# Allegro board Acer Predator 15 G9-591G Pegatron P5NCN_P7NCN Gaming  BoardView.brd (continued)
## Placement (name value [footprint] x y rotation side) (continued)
Q8804  -  [VX_SOIC_8P_50_197X236]  231.7 13.43 270 top
Q8805  -  [VX_SOT23_H43]  220.14 36.92 270 top
Q8806  -  [VX_SOT23_H43]  219.38 47.72 270 bottom
Q8807  -  [VX_SOT23_H43]  222.3 41.62 180 bottom
Q8900  -  [VX_SOP_8P_SPE_FAIRCHILD]  171.42 84.05 0 bottom
Q8901  -  [VX_SOP_8P_SPE_FAIRCHILD]  165.28 84.29 180 top
Q9100  -  [VX_SOT23_2D4_H44]  151.64 46.83 180 top
Q9101  -  [VX_SOT353]  148.51 44.8 180 top
Q9102  -  [VX_SOT353]  148.01 39.97 270 top
Q9103  -  [VX_SOT353]  143.31 32.98 270 top
Q9104  -  [VX_SOT353]  211 84.53 270 bottom
Q9105  -  [VX_SOT23_2D4_H44]  197.26 78.82 180 top
Q9200  -  [VX_SC70_S6]  139.37 49.67 270 top
R300  -  [VX_R0402_0OHM_SMALL]  176.9 151.37 270 top
R0300  -  [VX_R0402_SMALL]  61.77 150.97 180 top
R0301  -  [VX_R0402_SMALL]  63.83 145.13 270 top
R301  -  [VX_R0603_0OHM_H28_SMALL]  179 148.38 0 top
R0302  -  [VX_R0402_SMALL]  57.58 144.24 180 top
R0305  -  [VX_R0402_SMALL]  64.69 145.13 90 top
R0306  -  [VX_R0402_SMALL]  61.85 145.13 270 top
R0307  -  [VX_R0402_SMALL]  62.69 145.13 90 top
R400  -  [VX_R0603_0OHM_H28_SMALL]  208.12 150.59 90 top
R401  -  [VX_R0402_0OHM_SMALL]  209.19 150.26 270 top
R0500  -  [VX_R0402_SMALL]  9.73 126.79 90 top
R0501  -  [VX_R0402_0OHM_SMALL]  11.46 126.79 270 top
R0502  -  [VX_R0603_H24_SMALL]  14.5 126.56 90 top
R0503  -  [VX_R0402_SMALL]  8.84 126.79 270 top
R0504  -  [VX_R0402_SMALL]  67.62 122.67 180 bottom
R0505  -  [VX_R0603_H24_SMALL]  13.26 122.57 180 top
R0506  -  [VX_R0402_SMALL]  67.62 120.89 180 bottom
R0507  -  [VX_R0402_SMALL]  67.62 120 0 bottom
R0508  -  [VX_R0603_H24_SMALL]  14.07 128.84 180 top
R0509  -  [VX_R0402_SMALL]  16.05 128.44 90 top
R0510  -  [VX_R0402_SMALL]  11.86 123.71 180 top
R0511  -  [VX_R0402_SMALL]  12.31 130.08 180 top
R0600  -  [VX_R0402_SMALL]  67.62 121.78 180 bottom
R0700  -  [VX_R0402_SMALL]  16.08 140.68 90 top
R0701  -  [VX_R0402_SMALL]  20.19 145.41 0 top
R0702  -  [VX_R0402_SMALL]  24.05 143.65 0 top
R0703  -  [VX_R0402_SMALL]  21.07 140 180 top
R0704  -  [VX_R0402_SMALL]  14.91 124.6 0 bottom
R0705  -  [VX_R0402_SMALL]  14.28 141.87 180 bottom
R0706  -  [VX_R0402_SMALL]  15.97 151.5 90 bottom
R0707  -  [VX_R0402_SMALL]  17.2 147.07 0 top
R0708  -  [VX_R0402_SMALL]  17.2 148.99 180 top
R0709  -  [VX_R0402_SMALL]  17.32 142.76 180 top
R0710  -  [VX_R0402_SMALL]  16.97 140.68 90 top
R0712  -  [VX_R0402_SMALL]  19.23 142.25 0 top
R0713  -  [VX_R0402_SMALL]  24.05 137.43 180 top
R0714  -  [VX_R0402_SMALL]  19.23 141.37 0 top
R0715  -  [VX_R0402_SMALL]  12.5 139.84 90 bottom
R0717  -  [VX_R0402_SMALL]  19.23 148.05 180 top
R0718  -  [VX_R0402_SMALL]  21.44 137.51 270 top
R0719  -  [VX_R0402_SMALL]  14.28 140.98 180 bottom
R0723  -  [VX_R0402_SMALL]  22.4 143.65 180 top
R0724  -  [VX_R0402_SMALL]  19.23 140.48 0 top
R0725  -  [VX_R0402_SMALL]  17.32 144.16 180 top
R0726  -  [VX_R0402_SMALL]  19.23 143.4 0 top
R0727  -  [VX_R0402_SMALL]  17.45 151.4 0 bottom
R0728  -  [VX_R0402_SMALL]  15.24 129.4 180 bottom
R0729  -  [VX_R0402_SMALL]  72.57 124.81 180 bottom
R0730  -  [VX_R0402_SMALL]  72.57 123.92 180 bottom
R0731  -  [VX_R0402_SMALL]  17.27 153.3 0 bottom
R0733  -  [VX_R0402_SMALL]  17.45 154.45 180 bottom
R0734  -  [VX_R0402_0OHM_SMALL]  17.86 123.51 270 bottom
R0736  -  [VX_R0402_SMALL]  17.67 147.51 270 bottom
R0737  -  [VX_R0402_SMALL]  19.61 150.64 0 top
R0738  -  [VX_R0402_SMALL]  16.82 149.24 270 bottom
R0739  -  [VX_R0402_SMALL]  16.83 147.51 270 bottom
R0740  -  [VX_R0402_SMALL]  17.27 152.29 180 bottom
R0741  -  [VX_R0402_SMALL]  17.32 145.56 180 bottom
R0742  -  [VX_R0402_SMALL]  16.68 143.71 90 bottom
R0743  -  [VX_R0402_SMALL]  55.68 140.3 90 top
R0744  -  [VX_R0402_SMALL]  14.28 142.76 0 bottom
R0745  -  [VX_R0402_SMALL]  21.07 138.75 0 top
R0746  -  [VX_R0201_H10]  19.23 155.46 180 bottom
R0747  -  [VX_R0402_SMALL]  16.82 150.26 90 top
R0748  -  [VX_R0402_0OHM_SMALL]  116.51 50.77 90 top
R0749  -  [VX_R0402_0OHM_SMALL]  115.62 50.77 90 top
R0750  -  [VX_R0402_0OHM_SMALL]  112.37 54.87 0 top
R0751  -  [VX_R0402_SMALL]  114.1 54.87 0 top
R0900  -  [VX_R0603_0OHM_H28_SMALL]  43.23 143.88 270 top
R0901  -  [VX_R0603_0OHM_H28_SMALL]  42.01 143.88 270 top
R1000  -  [VX_R0603_0OHM_H28_SMALL]  27.99 139.08 180 top
R1001  -  [VX_R0402_0OHM_SMALL]  68.55 125.04 270 bottom
R1002  -  [VX_R0603_0OHM_H28_SMALL]  25.58 143.78 270 top
R1003  -  [VX_R0603_0OHM_H28_SMALL]  27.99 136.54 180 top
R1004  -  [VX_R0402_SMALL]  25.32 141.87 90 top
R1005  -  [VX_R0402_0OHM_SMALL]  24.46 141.87 270 top
R1006  -  [VX_R0603_0OHM_H28_SMALL]  27.99 137.81 180 top
R1007  -  [VX_R0603_0OHM_H28_SMALL]  12.98 129.91 0 bottom
R1008  -  [VX_R0603_0OHM_H28_SMALL]  27.99 135.27 180 top
R1009  -  [VX_R0402_SMALL]  22.33 137.51 90 top
R1010  -  [VX_R0402_0OHM_SMALL]  21.87 136.24 0 top
R1011  -  [VX_R0603_0OHM_H28_SMALL]  22.56 133.52 0 top
R1012  -  [VX_R0603_0OHM_H28_SMALL]  21.78 149.24 90 top
R1013  -  [VX_R0402_SMALL]  34.09 132.6 0 top
R1014  -  [VX_R0402_SMALL]  19.23 147.07 0 top
R1015  -  [VX_R0402_SMALL]  15.84 143.71 90 bottom
R1016  -  [VX_R0402_SMALL]  17.51 143.71 90 bottom
R1017  -  [VX_R1206_H31]  90.98 107.71 180 top
R1018  -  [VX_R0402_0OHM_SMALL]  22.71 128.16 90 top
R1101  -  [VX_R0402_SMALL]  241.7 29.23 270 bottom
R1102  -  [VX_R0402_SMALL]  230.94 44.29 180 bottom
R1103  -  [VX_R0402_SMALL]  227.25 55.21 90 top
R1104  -  [VX_R0402_SMALL]  224.21 55.21 90 top
R1105  -  [VX_R0402_SMALL]  222.68 50.64 90 top
R1106  -  [VX_R0402_SMALL]  226.24 55.21 90 top
R1107  -  [VX_R0402_SMALL]  245.04 36.75 0 bottom
R1108  -  [VX_R0402_SMALL]  235.88 30.33 90 bottom
R1109  -  [VX_R0402_SMALL]  235.13 38.96 0 bottom
R1110  -  [VX_R0402_SMALL]  235.13 39.84 0 bottom
R1111  -  [VX_R0402_SMALL]  228.86 38.95 180 top
R1112  -  [VX_R0402_SMALL]  233.35 40.99 0 bottom
R1113  -  [VX_R0402_SMALL]  230.94 40.48 180 bottom
R1114  -  [VX_R0402_SMALL]  230.94 42.26 180 bottom
R1115  -  [VX_R0402_SMALL]  230.94 41.37 180 bottom
R1118  -  [VX_R0402_SMALL]  249.86 35.2 270 top
R1119  -  [VX_R0402_SMALL]  230.91 41.89 0 top
R1120  -  [VX_R0402_SMALL]  228.78 45.81 180 bottom
R1121  -  [VX_R0402_0OHM_SMALL]  230.94 45.18 0 bottom
R1122  -  [VX_R0402_SMALL]  251.77 34.89 270 top
R1123  -  [VX_R0402_SMALL]  244.4 27.53 180 bottom
R1124  -  [VX_R0402_SMALL]  246.18 27.53 0 bottom
R1125  -  [VX_R0402_SMALL]  241.1 42.64 180 top
R1126  -  [VX_R0402_SMALL]  251.64 36.29 0 top
R1127  -  [VX_R0402_SMALL]  248.97 35.2 270 top
R1128  -  [VX_R0402_SMALL]  230.94 45.69 180 top
R1129  -  [VX_R0402_SMALL]  231.3 39.44 180 top
R1130  -  [VX_R0402_SMALL]  244.15 43.15 180 top
R1131  -  [VX_R0402_SMALL]  230.94 46.58 180 top
R1132  -  [VX_R0402_SMALL]  230.94 43.91 180 top
R1133  -  [VX_R0402_SMALL]  230.94 47.85 0 bottom
R1134  -  [VX_R0402_SMALL]  246.94 37.15 270 bottom
R1135  -  [VX_R0402_SMALL]  230.94 44.8 180 top
R1138  -  [VX_R0402_SMALL]  236.27 41.75 180 bottom
R1139  -  [VX_R0402_SMALL]  235.1 43.13 180 top
R1140  -  [VX_R0402_SMALL]  239.42 42.36 90 top
R1141  -  [VX_R0402_SMALL]  237.67 42.38 90 top
R1142  -  [VX_R0402_SMALL]  237.8 38.32 90 bottom
R1143  -  [VX_R0402_SMALL]  236.14 37.94 180 bottom
R1144  -  [VX_R0402_SMALL]  229.12 43.41 270 bottom
R1145  -  [VX_R0402_SMALL]  232.59 47.08 270 bottom
R1146  -  [VX_R0402_SMALL]  232.97 42.41 180 top
R1147  -  [VX_R0402_SMALL]  240.97 43.53 180 top
R1148  -  [VX_R0402_0OHM_SMALL]  233.04 38.96 0 bottom
R1149  -  [VX_R0402_0OHM_SMALL]  233.04 39.84 0 bottom
R1150  -  [VX_R0402_0OHM_SMALL]  230.94 46.07 180 bottom
R1151  -  [VX_R0402_0OHM_SMALL]  230.94 46.96 180 bottom
R1152  -  [VX_R0402_0OHM_SMALL]  235.1 42.24 180 top
R1153  -  [VX_R0402_0OHM_SMALL]  230.94 47.59 180 top
R1154  -  [VX_R0402_SMALL]  232.92 30.7 180 bottom
R1155  -  [VX_R0402_SMALL]  234.67 30.7 0 bottom
R1159  -  [VX_R0603_0OHM_H28_SMALL]  253.75 36.42 90 top
R1160  -  [VX_R0603_0OHM_H28_SMALL]  249.23 38.83 270 bottom
R1161  -  [VX_R0402_SMALL]  232.97 41.55 0 top
R1162  -  [VX_R0402_0OHM_SMALL]  234.49 54.53 270 bottom
R1164  -  [VX_R0603_0OHM_H28_SMALL]  248.59 36.16 0 bottom
R1202  -  [VX_R0402_0OHM_SMALL]  251.13 50.26 180 top
R1204  -  [VX_R0402_0OHM_SMALL]  251.13 51.93 180 top
R1211  -  [VX_R0402_0OHM_SMALL]  237.16 45.69 0 top
R1218  -  [VX_R0402_SMALL]  239.45 45.69 0 top
R1219  -  [VX_R0402_0OHM_SMALL]  249.61 49.88 270 top
R1220  -  [VX_R0402_0OHM_SMALL]  248.72 49.88 270 top
R1222  -  [VX_R0402_SMALL]  230.3 55.16 180 top
R1223  -  [VX_R0402_0OHM_SMALL]  230.3 56.05 0 top
R1224  -  [VX_R0402_SMALL]  237.13 49.9 0 top
R1225  -  [VX_R0402_SMALL]  237.13 49.04 0 top
R1226  -  [VX_R0402_SMALL]  237.16 46.7 0 top
R1227  -  [VX_R0402_SMALL]  234.07 48.56 180 top
R1228  -  [VX_R0402_SMALL]  232.41 50 270 top
R1229  -  [VX_R0402_SMALL]  243.38 55.59 90 top
R1230  -  [VX_R0402_SMALL]  233.3 50 270 top
R1231  -  [VX_R0402_SMALL]  235.08 50 270 top
R1232  -  [VX_R0402_SMALL]  234.19 50 270 top
R1233  -  [VX_R0402_SMALL]  249.48 45.31 0 top
R1234  -  [VX_R0402_SMALL]  249.48 46.32 0 top
R1235  -  [VX_R0402_SMALL]  247.83 46.96 0 top
R1236  -  [VX_R0402_SMALL]  250.11 47.21 0 top
R1237  -  [VX_R0603_0OHM_H28_SMALL]  234.59 47.08 0 bottom
R1238  -  [VX_R0603_0OHM_H28_SMALL]  234.59 45.81 0 bottom
R1239  -  [VX_R0402_0OHM_SMALL]  230.3 56.99 0 top
R1301  -  [VX_R0402_SMALL]  212.13 48.15 270 top
R1302  -  [VX_R0402_SMALL]  208.46 60.34 0 top
R1303  -  [VX_R0402_0OHM_SMALL]  218.05 58.87 180 top
R1304  -  [VX_R0402_SMALL]  211 48.15 90 top
R1305  -  [VX_R0402_SMALL]  210.11 48.15 270 top
R1306  -  [VX_R0402_SMALL]  206.05 55.77 270 top
R1307  -  [VX_R0402_SMALL]  207.06 55.77 90 top
R1308  -  [VX_R0402_SMALL]  209.22 47.72 90 top
R1309  -  [VX_R0402_SMALL]  208.33 48.22 270 top
R1314  -  [VX_R0402_SMALL]  216.25 59.48 270 top
R1315  -  [VX_R0402_SMALL]  214.4 59.4 270 top
R1316  -  [VX_R0402_SMALL]  215.39 61.01 270 top
R1317  -  [VX_R0402_SMALL]  213.86 47.9 90 top
R1320  -  [VX_R0402_SMALL]  214.4 61.01 270 top
R1321  -  [VX_R0402_SMALL]  214.68 48.02 270 top
R1401  -  [VX_R0402_SMALL]  210.03 34.06 90 top
R1402  -  [VX_R0402_SMALL]  205.41 41.54 270 top
R1403  -  [VX_R0402_SMALL]  211.07 32.41 90 top
R1404  -  [VX_R0402_SMALL]  206.3 41.54 90 top
R1405  -  [VX_R0402_SMALL]  210.03 32.41 90 top
R1406  -  [VX_R0402_SMALL]  211.07 34.06 90 top
R1407  -  [VX_R0402_SMALL]  206.31 44.95 270 top
R1408  -  [VX_R0402_0OHM_SMALL]  216.33 35.32 180 top
R1411  -  [VX_R0402_SMALL]  213.67 33.92 270 top
R1414  -  [VX_R0402_SMALL]  215.32 45.23 270 top
R1415  -  [VX_R0402_SMALL]  214.3 45.23 270 top
R1416  -  [VX_R0402_SMALL]  213.41 45.23 90 top
R1417  -  [VX_R0402_SMALL]  214.68 33.92 270 top
R1600  -  [VX_R0402_SMALL]  66.22 82.06 0 bottom
R1601  -  [VX_R0402_SMALL]  67.67 84.72 180 bottom
R1604  -  [VX_R0402_0OHM_SMALL]  95.76 88.86 0 bottom
R1605  -  [VX_R0402_0OHM_SMALL]  94.08 88.86 180 bottom
R1606  -  [VX_R0402_0OHM_SMALL]  82.47 82.44 180 bottom
R1607  -  [VX_R0402_0OHM_SMALL]  92 81.93 0 bottom
R1608  -  [VX_R0402_0OHM_SMALL]  92 83.83 0 bottom
R1609  -  [VX_R0402_0OHM_SMALL]  80.7 82.44 180 bottom
R1610  -  [VX_R0402_SMALL]  76.38 85.23 0 bottom
R1612  -  [VX_R0402_SMALL]  76.38 84.34 180 bottom
R1613  -  [VX_R0402_0OHM_SMALL]  95.76 87.98 180 bottom
R1614  -  [VX_R0402_0OHM_SMALL]  94.08 87.92 0 bottom
R1615  -  [VX_R0402_0OHM_SMALL]  82.47 81.55 0 bottom
R1617  -  [VX_R0402_0OHM_SMALL]  92 81.04 180 bottom
R1618  -  [VX_R0402_0OHM_SMALL]  92 82.95 180 bottom
R1619  -  [VX_R0402_0OHM_SMALL]  80.7 81.55 0 bottom
R1620  -  [VX_R0402_0OHM_SMALL]  76.38 83.45 180 bottom
R1621  -  [VX_R0402_0OHM_SMALL]  78.71 83.45 0 bottom
R1622  -  [VX_R1206_H31]  90.09 108.46 180 bottom
R1623  -  [VX_R0402_SMALL]  11.61 120.11 90 bottom
R1624  -  [VX_R0402_SMALL]  12.5 120.11 90 bottom
R1700  -  [VX_R0402_SMALL]  70.21 54.75 0 bottom
R1701  -  [VX_R0402_SMALL]  107.47 62.3 0 bottom
R1704  -  [VX_R0402_0OHM_SMALL]  92.23 54.73 0 bottom
R1705  -  [VX_R0402_0OHM_SMALL]  100.66 54.78 180 bottom
R1706  -  [VX_R0402_0OHM_SMALL]  78.51 54.75 180 bottom
R1707  -  [VX_R0402_0OHM_SMALL]  108.26 54.14 90 top
R1708  -  [VX_R0402_0OHM_SMALL]  107.37 54.14 90 top
R1709  -  [VX_R0402_0OHM_SMALL]  107.47 59.32 0 bottom
R1710  -  [VX_R0402_SMALL]  35.23 88.91 0 bottom
R1712  -  [VX_R0402_0OHM_SMALL]  108.26 55.74 90 top
R1713  -  [VX_R0402_0OHM_SMALL]  107.37 55.74 90 top
R1714  -  [VX_R0402_SMALL]  35.23 88.03 180 bottom
R1715  -  [VX_R0402_0OHM_SMALL]  93.88 54.73 0 bottom
R1716  -  [VX_R0402_0OHM_SMALL]  99.03 54.78 180 bottom
R1717  -  [VX_R0402_0OHM_SMALL]  76.86 54.75 180 bottom
R1719  -  [VX_R0402_0OHM_SMALL]  107.47 60.21 180 bottom
R1720  -  [VX_R0402_0OHM_SMALL]  35.23 87.14 180 bottom
R1721  -  [VX_R0402_0OHM_SMALL]  37.01 87.14 0 bottom
R1722  -  [VX_R1206_H31]  107.77 71.64 270 bottom
R2000  -  [VX_R0402_SMALL]  170.38 67.58 90 top
R2001  -  [VX_R0402_0OHM_SMALL]  169.56 67.58 270 bottom
R2100  -  [VX_R0402_SMALL]  174.42 36.34 90 bottom
R2101  -  [VX_R0402_0OHM_SMALL]  182.93 68.59 270 top
R2102  -  [VX_R0402_SMALL]  173.25 33.67 90 bottom
R2103  -  [VX_R0402_SMALL]  172.43 33.67 90 bottom
R2104  -  [VX_R0402_SMALL]  171.6 33.67 90 bottom
R2105  -  [VX_R0402_SMALL]  170.87 36.34 90 top
R2106  -  [VX_R0402_SMALL]  170.76 33.67 90 bottom
R2107  -  [VX_R0402_SMALL]  169.6 36.34 90 top
R2108  -  [VX_R0402_SMALL]  167.56 36.34 90 top
R2110  -  [VX_R0402_SMALL]  170.87 33.67 270 top
R2111  -  [VX_R0402_SMALL]  169.6 33.67 270 top
R2112  -  [VX_R0402_SMALL]  168.71 36.34 270 top
R2113  -  [VX_R0402_SMALL]  164.01 33.67 90 top
R2114  -  [VX_R0402_SMALL]  165.79 36.34 90 bottom
R2115  -  [VX_R0402_SMALL]  164.64 33.42 270 bottom
R2116  -  [VX_R0402_SMALL]  164.9 36.34 90 bottom
R2117  -  [VX_R0402_SMALL]  169.6 36.34 90 bottom
R2118  -  [VX_R0402_SMALL]  170.87 36.34 90 bottom
R2119  -  [VX_R0402_SMALL]  166.68 36.34 90 top
R2120  -  [VX_R0402_SMALL]  169.93 33.67 90 bottom
R2121  -  [VX_R0402_SMALL]  169.09 33.67 270 bottom
R2122  -  [VX_R0402_SMALL]  164.01 36.34 90 top
R2123  -  [VX_R0402_SMALL]  156.95 33.98 270 top
R2124  -  [VX_R0402_SMALL]  167.56 36.34 90 bottom
R2125  -  [VX_R0402_SMALL]  164.9 36.34 90 top
R2127  -  [VX_R0402_SMALL]  176.96 67.45 90 top
R2128  -  [VX_R0402_SMALL]  181.81 70.26 270 top
R2129  -  [VX_R0402_SMALL]  182.93 70.25 270 top
R2131  -  [VX_R0402_SMALL]  163.12 36.34 90 top
R2132  -  [VX_R0402_SMALL]  165.79 33.67 270 bottom
R2133  -  [VX_R0402_SMALL]  167.56 33.67 90 bottom
R2134  -  [VX_R0402_SMALL]  166.68 36.34 90 bottom
R2135  -  [VX_R0402_SMALL]  156.01 36.34 90 top
R2136  -  [VX_R0402_SMALL]  155.12 36.34 90 top
R2140  -  [VX_R0402_0OHM_SMALL]  158.67 36.34 270 top
R2141  -  [VX_R0402_SMALL]  168.71 36.34 270 bottom
R2142  -  [VX_R0402_SMALL]  169.47 41.54 270 top
R2143  -  [VX_R0402_SMALL]  165.91 33.67 270 top
R2144  -  [VX_R0402_SMALL]  168.71 33.67 90 top
R2145  -  [VX_R0402_SMALL]  166.68 33.67 270 bottom
R2146  -  [VX_R0402_SMALL]  164.01 36.34 270 bottom
R2148  -  [VX_R0402_SMALL]  157.79 36.34 270 top
R2149  -  [VX_R0402_SMALL]  178.74 67.45 270 top
R2150  -  [VX_R0402_0OHM_SMALL]  157.8 33.98 270 top
R2151  -  [VX_R0402_SMALL]  180.47 70.25 270 top
R2152  -  [VX_R0402_SMALL]  179.38 67.28 270 bottom
R2153  -  [VX_R0402_SMALL]  179.63 70.25 270 top
R2154  -  [VX_R0402_SMALL]  182.3 70.25 270 bottom
R2155  -  [VX_R0402_SMALL]  183.19 70.25 270 bottom
R2156  -  [VX_R0402_0OHM_SMALL]  181.72 68.33 270 top
R2157  -  [VX_R0402_SMALL]  172.64 36.34 90 bottom
R2158  -  [VX_R0402_0OHM_SMALL]  179.63 68.59 270 top
R2159  -  [VX_R0402_0OHM_SMALL]  180.47 68.59 270 top
R2160  -  [VX_R0402_0OHM_SMALL]  182.09 67.07 270 bottom
R2161  -  [VX_R0402_0OHM_SMALL]  182.98 67.07 270 bottom
R2162  -  [VX_R0402_SMALL]  165.05 33.67 90 top
R2163  -  [VX_R0402_SMALL]  212.95 48.15 270 top
R2164  -  [VX_R0402_SMALL]  165.79 36.34 90 top
R2201  -  [VX_R0402_SMALL]  155.22 36.34 270 bottom
R2202  -  [VX_R0402_SMALL]  188.27 60.09 180 top
R2203  -  [VX_R0402_SMALL]  185.6 57.04 0 top
R2204  -  [VX_R0402_SMALL]  156.01 33.67 90 bottom
R2205  -  [VX_R0402_SMALL]  156.06 36.34 90 bottom
R2206  -  [VX_R0402_SMALL]  185.6 57.93 0 top
R2207  -  [VX_R0402_SMALL]  163.37 33.67 270 bottom
R2208  -  [VX_R0402_SMALL]  163.12 36.34 90 bottom
R2209  -  [VX_R0402_SMALL]  162.23 36.34 270 top
R2210  -  [VX_R0402_SMALL]  155.12 33.67 90 bottom
R2218  -  [VX_R0402_0OHM_SMALL]  188.27 61.1 180 top
R2219  -  [VX_R0402_0OHM_SMALL]  185.6 53.86 180 top
R2220  -  [VX_R0402_0OHM_SMALL]  188.27 53.99 180 top
R2221  -  [VX_R0402_0OHM_SMALL]  185.6 55.13 180 top
R2222  -  [VX_R0402_0OHM_SMALL]  185.6 57.11 180 bottom
R2223  -  [VX_R0402_0OHM_SMALL]  188.27 57.42 180 bottom
R2224  -  [VX_R0402_0OHM_SMALL]  188.27 57.42 180 top
R2225  -  [VX_R0402_0OHM_SMALL]  188.27 58.31 180 top
R2226  -  [VX_R0402_0OHM_SMALL]  190.93 55.89 180 bottom
R2227  -  [VX_R0402_SMALL]  188.27 56.53 180 bottom
R2228  -  [VX_R0402_SMALL]  170.49 70.25 90 bottom
R2229  -  [VX_R0402_0OHM_SMALL]  190.93 47.13 180 bottom
R2230  -  [VX_R0402_0OHM_SMALL]  193.73 47.13 180 bottom
R2231  -  [VX_R0402_0OHM_SMALL]  188.27 48.33 180 bottom
R2232  -  [VX_R0402_0OHM_SMALL]  186.11 47.28 180 bottom
R2233  -  [VX_R0402_0OHM_SMALL]  193.73 48.02 180 bottom
R2234  -  [VX_R0402_0OHM_SMALL]  193.73 49.04 180 bottom
R2235  -  [VX_R0402_SMALL]  171.5 70.25 90 bottom
R2236  -  [VX_R0402_SMALL]  185.6 55.35 180 bottom
R2237  -  [VX_R0402_SMALL]  188.52 54.75 180 bottom
R2238  -  [VX_R0402_SMALL]  190.93 54.12 180 bottom
R2239  -  [VX_R0402_SMALL]  193.22 47.26 180 top
R2240  -  [VX_R0402_SMALL]  190.93 55.01 180 bottom
R2241  -  [VX_R0402_SMALL]  190.93 53.23 180 bottom
R2242  -  [VX_R0402_SMALL]  188.27 53.86 180 bottom
R2243  -  [VX_R0402_SMALL]  156.9 36.34 90 top
R2244  -  [VX_R0402_SMALL]  153.34 33.67 90 bottom
R2245  -  [VX_R0402_SMALL]  152.45 33.67 90 bottom
R2246  -  [VX_R0402_SMALL]  160.45 33.67 90 top
R2247  -  [VX_R0402_SMALL]  159.56 33.42 90 top
R2248  -  [VX_R0402_SMALL]  160.45 36.34 90 top
R2249  -  [VX_R0402_SMALL]  156.9 33.42 90 bottom
R2250  -  [VX_R0402_SMALL]  185.6 56.2 180 bottom
R2251  -  [VX_R0402_SMALL]  188.27 52.57 180 top
R2255  -  [VX_R0402_SMALL]  153.26 36.34 270 bottom
R2256  -  [VX_R0402_SMALL]  152.45 36.34 270 bottom
R2257  -  [VX_R0402_SMALL]  159.56 36.34 270 top
R2258  -  [VX_R0402_SMALL]  156.9 36.34 270 bottom
R2259  -  [VX_R0402_SMALL]  165.41 41.54 90 top
R2260  -  [VX_R0402_SMALL]  166.29 41.54 270 top
R2261  -  [VX_R0402_SMALL]  160.45 36.34 90 bottom
R2262  -  [VX_R0402_SMALL]  181.04 54.21 0 top
R2263  -  [VX_R0402_SMALL]  188.52 55.64 0 bottom
R2264  -  [VX_R0402_SMALL]  185.6 56.02 180 top
R2265  -  [VX_R0402_SMALL]  190.83 55.79 180 top
R2300  -  [VX_R0402_SMALL]  187.63 67.58 270 bottom
R2301  -  [VX_R0402_SMALL]  185.85 67.58 270 bottom
R2302  -  [VX_R0402_SMALL]  172.64 36.34 90 top
R2303  -  [VX_R0402_SMALL]  174.42 36.32 90 top
R2304  -  [VX_R0402_SMALL]  173.53 36.34 90 top
R2305  -  [VX_R0402_SMALL]  173.53 36.34 90 bottom
R2306  -  [VX_R0402_SMALL]  186.74 67.58 270 bottom
R2307  -  [VX_R0402_SMALL]  173.58 67.1 270 bottom
R2308  -  [VX_R0402_SMALL]  184.38 67.07 270 bottom
R2309  -  [VX_R0402_SMALL]  173.3 33.68 90 top
R2310  -  [VX_R0402_SMALL]  167.95 29.7 180 bottom
R2311  -  [VX_R0402_SMALL]  174.47 67.1 270 bottom
R2312  -  [VX_R0402_SMALL]  175.61 33.67 90 top
R2313  -  [VX_R0402_SMALL]  175.31 36.32 90 top
R2314  -  [VX_R0402_SMALL]  178.69 33.68 90 bottom
R2315  -  [VX_R0402_SMALL]  176.43 36.33 90 top
R2316  -  [VX_R0402_SMALL]  172.46 33.68 90 top
R2317  -  [VX_R0402_SMALL]  176.53 33.68 90 bottom
R2318  -  [VX_R0402_SMALL]  177.65 36.35 90 bottom
R2319  -  [VX_R0402_SMALL]  176.43 36.34 90 bottom
R2322  -  [VX_R0402_0OHM_SMALL]  177.85 67.45 270 top
R2325  -  [VX_R0402_0OHM_SMALL]  177.72 70.25 90 bottom
R2326  -  [VX_R0402_SMALL]  172.39 70.25 90 bottom
R2327  -  [VX_R0402_SMALL]  181.41 33.67 90 top
R2328  -  [VX_R0402_SMALL]  182.63 33.67 90 top
R2329  -  [VX_R0402_SMALL]  184.46 33.67 90 bottom
R2330  -  [VX_R0402_SMALL]  180.52 33.67 90 top
R2331  -  [VX_R0402_SMALL]  178.66 33.67 90 top
R2332  -  [VX_R0402_SMALL]  182.55 33.67 90 bottom
R2333  -  [VX_R0402_SMALL]  179.68 33.67 90 top
R2334  -  [VX_R0402_SMALL]  183.52 33.67 90 top
R2335  -  [VX_R0402_SMALL]  190.93 50.05 180 top
R2343  -  [VX_R0402_0OHM_SMALL]  177.34 67.28 270 bottom
R2344  -  [VX_R0402_0OHM_SMALL]  175.95 70.25 90 bottom
R2345  -  [VX_R0402_0OHM_SMALL]  176.35 67.45 270 bottom
R2346  -  [VX_R0402_0OHM_SMALL]  176.84 70.25 90 bottom
R2347  -  [VX_R0402_SMALL]  179.38 36.34 270 top
R2348  -  [VX_R0402_SMALL]  183.26 36.34 90 top
R2349  -  [VX_R0402_SMALL]  188.27 50.05 0 top
R2350  -  [VX_R0402_SMALL]  175.46 67.45 90 bottom
R2357  -  [VX_R0402_SMALL]  181.41 33.67 90 bottom
R2358  -  [VX_R0402_SMALL]  181.41 36.34 90 bottom
R2360  -  [VX_R0402_SMALL]  177.37 33.68 90 bottom
R2361  -  [VX_R0402_SMALL]  175.53 36.34 90 bottom
R2363  -  [VX_R0402_SMALL]  175.67 33.68 90 bottom
R2364  -  [VX_R0402_SMALL]  177.29 33.67 90 top
R2365  -  [VX_R0402_SMALL]  166.83 33.67 90 top
R2369  -  [VX_R0402_SMALL]  180.58 33.67 90 bottom
R2370  -  [VX_R0402_SMALL]  178.59 31.86 0 top
R2371  -  [VX_R0402_SMALL]  180.52 36.34 90 bottom
R2372  -  [VX_R0402_SMALL]  177.5 36.34 90 top
R2375  -  [VX_R0402_0OHM_SMALL]  171.47 38.14 270 top
R2376  -  [VX_R0402_0OHM_SMALL]  172.36 38.14 90 top
R2377  -  [VX_R0402_0OHM_SMALL]  176.45 33.67 90 top
R2378  -  [VX_R0402_SMALL]  186.07 72.9 180 top
R2379  -  [VX_R0402_SMALL]  175.29 37.56 180 top
R2380  -  [VX_R0402_SMALL]  176.33 42.77 90 top
R2381  -  [VX_R0402_SMALL]  171.75 32.01 180 bottom
R2382  -  [VX_R0402_0OHM_SMALL]  167.55 30.95 270 bottom
R2400  -  [VX_R0402_SMALL]  185.6 50.26 180 bottom
R2401  -  [VX_R0402_SMALL]  185.6 47.26 180 top
R2402  -  [VX_R0402_SMALL]  188.27 47.51 180 top
R2403  -  [VX_R0402_SMALL]  185.53 49.53 180 top
R2404  -  [VX_R0402_SMALL]  185.6 49.42 180 bottom
R2405  -  [VX_R0402_SMALL]  190.93 49.42 180 bottom
R2406  -  [VX_R0402_SMALL]  193.22 50 180 top
R2407  -  [VX_R0402_SMALL]  193.22 48.27 180 top
R2408  -  [VX_R0402_SMALL]  188.27 52.97 180 bottom
R2409  -  [VX_R0402_SMALL]  188.27 52.08 180 bottom
R2410  -  [VX_R0402_SMALL]  185.6 52.08 180 top
R2411  -  [VX_R0402_SMALL]  185.75 51.2 180 top
R2412  -  [VX_R0402_SMALL]  185.6 51.27 180 bottom
R2413  -  [VX_R0402_SMALL]  188.27 49.42 180 bottom
R2414  -  [VX_R0402_SMALL]  190.93 41.7 180 bottom
R2415  -  [VX_R0402_SMALL]  193.73 42.05 180 bottom
R2416  -  [VX_R0402_SMALL]  190.68 42.81 180 top
R2417  -  [VX_R0402_SMALL]  190.93 42.59 180 bottom
R2418  -  [VX_R0402_SMALL]  185.6 48.27 180 top
R2419  -  [VX_R0402_SMALL]  188.27 51.73 180 top
R2420  -  [VX_R0402_SMALL]  185.6 53.08 180 bottom
R2421  -  [VX_R0402_SMALL]  191.6 52.3 180 bottom
R2422  -  [VX_R0402_SMALL]  185.6 52.97 180 top
R2423  -  [VX_R0402_SMALL]  185.6 52.19 180 bottom
R2424  -  [VX_R0402_SMALL]  188.27 48.4 180 top
R2425  -  [VX_R0402_SMALL]  188.27 51.2 180 bottom
R2426  -  [VX_R0402_SMALL]  190.93 49.16 180 top
R2427  -  [VX_R0402_SMALL]  190.93 48.27 180 top
R2428  -  [VX_R0402_SMALL]  190.68 44.54 180 top
R2429  -  [VX_R0402_SMALL]  190.93 47.39 180 top
R2430  -  [VX_R0402_SMALL]  185.6 46.37 180 bottom
R2431  -  [VX_R0402_SMALL]  185.6 46.37 180 top
R2432  -  [VX_R0402_SMALL]  188.27 46.62 180 top
R2433  -  [VX_R0402_SMALL]  193.73 44.72 180 bottom
R2434  -  [VX_R0402_SMALL]  188.27 45.73 180 top
R2435  -  [VX_R0402_SMALL]  185.6 44.34 180 top
R2436  -  [VX_R0402_SMALL]  185.6 44.85 180 bottom
R2437  -  [VX_R0402_SMALL]  190.93 45.73 180 bottom
R2438  -  [VX_R0402_0OHM_SMALL]  175.95 67.45 90 top
R2439  -  [VX_R0402_0OHM_SMALL]  190.93 57.67 0 bottom
R2440  -  [VX_R0402_0OHM_SMALL]  186.61 62.88 90 top
R2441  -  [VX_R0402_0OHM_SMALL]  184.07 62.4 90 top
R2442  -  [VX_R0402_SMALL]  188.27 59.2 180 top
R2443  -  [VX_R0402_0OHM_SMALL]  191.19 59.53 180 bottom
R2444  -  [VX_R0402_SMALL]  188.27 59.11 180 bottom
R2445  -  [VX_R0402_SMALL]  188.27 60.81 180 bottom
R2446  -  [VX_R0402_SMALL]  188.27 59.96 180 bottom
R2447  -  [VX_R0402_SMALL]  181.92 66.56 270 top
R2448  -  [VX_R0402_SMALL]  191.19 61.1 180 bottom
R2449  -  [VX_R0402_SMALL]  190.93 50.26 180 bottom
R2450  -  [VX_R0402_SMALL]  169.6 70.25 270 bottom
R2451  -  [VX_R0402_SMALL]  178.49 67.28 270 bottom
R2452  -  [VX_R0402_SMALL]  187.76 64.02 90 top
R2454  -  [VX_R0402_SMALL]  170.38 67.58 90 bottom
R2457  -  [VX_R0402_0OHM_SMALL]  188.27 50.92 0 top
R2458  -  [VX_R0402_SMALL]  174.8 67.45 270 top
R2459  -  [VX_R0402_SMALL]  185.6 59.2 180 top
R2460  -  [VX_R0402_SMALL]  188.27 50.26 0 bottom
R2462  -  [VX_R0402_0OHM_SMALL]  173.43 70.25 90 bottom
R2463  -  [VX_R0402_SMALL]  193.73 42.94 180 bottom
R2464  -  [VX_R0402_SMALL]  195.38 43.83 180 bottom
R2465  -  [VX_R0402_SMALL]  188.27 44.85 180 bottom
R2466  -  [VX_R0402_SMALL]  192.46 41.62 270 bottom
R2467  -  [VX_R0402_SMALL]  190.68 43.7 180 top
R2469  -  [VX_R0402_SMALL]  190.93 44.85 180 bottom
R2470  -  [VX_R0402_SMALL]  190.93 43.98 180 bottom
R2471  -  [VX_R0402_SMALL]  188.29 43.23 180 top
R2472  -  [VX_R0402_SMALL]  184.07 42.77 180 top
R2473  -  [VX_R0402_SMALL]  188.29 42.4 180 top
R2474  -  [VX_R0402_SMALL]  171.42 67.58 90 bottom
R2475  -  [VX_R0402_SMALL]  184.96 62.4 90 top
R2476  -  [VX_R0402_SMALL]  182.8 64.4 270 top
R2477  -  [VX_R0402_SMALL]  184.07 70.12 90 top
R2478  -  [VX_R0402_SMALL]  187.76 62.37 270 top
R2479  -  [VX_R0402_SMALL]  180.77 67.53 90 bottom
R2481  -  [VX_R0402_SMALL]  188.27 44.8 0 top
R2483  -  [VX_R0402_0OHM_SMALL]  200.2 40.73 0 bottom
R2484  -  [VX_R0402_SMALL]  193.73 43.83 0 bottom
R2485  -  [VX_R0402_0OHM_SMALL]  188.65 64.02 270 top
R2488  -  [VX_R0402_0OHM_SMALL]  184.96 70.12 270 top
R2489  -  [VX_R0402_0OHM_SMALL]  190.68 69.86 180 bottom
R2490  -  [VX_R0402_SMALL]  45.01 26.51 270 top
R2491  -  [VX_R0402_0OHM_SMALL]  189.28 67.07 90 bottom
R2492  -  [VX_R0402_0OHM_SMALL]  182.8 66.56 270 top
R2493  -  [VX_R0402_0OHM_SMALL]  196.14 66.44 90 bottom
R2494  -  [VX_R0402_0OHM_SMALL]  197.03 66.44 90 bottom
R2495  -  [VX_R0402_0OHM_SMALL]  198.5 48.86 180 bottom
R2496  -  [VX_R0402_0OHM_SMALL]  198.17 47.77 180 bottom
R2497  -  [VX_R0402_SMALL]  198.17 46.75 0 bottom
R2498  -  [VX_R0402_0OHM_SMALL]  200.76 49.5 0 bottom
R2499  -  [VX_R0402_0OHM_SMALL]  193.22 49.16 0 top
R2500  -  [VX_R0402_0OHM_SMALL]  159.56 69.48 90 bottom
R2501  -  [VX_R0402_0OHM_SMALL]  160.45 69.48 90 bottom
R2502  -  [VX_R0402_0OHM_SMALL]  165.53 64.28 90 top
R2503  -  [VX_R0402_0OHM_SMALL]  159.06 67.2 90 bottom
R2505  -  [VX_R0402_0OHM_SMALL]  158.17 67.2 90 bottom
R2507  -  [VX_R0402_0OHM_SMALL]  163.12 70.25 90 bottom
R2508  -  [VX_R0402_0OHM_SMALL]  164.01 70.25 90 bottom
R2509  -  [VX_R0402_0OHM_SMALL]  166.42 64.28 90 top
R2510  -  [VX_R0402_0OHM_SMALL]  161.34 71.47 90 bottom
R2511  -  [VX_R0402_0OHM_SMALL]  162.23 71.47 90 bottom
R2512  -  [VX_R0402_SMALL]  156.92 67.15 270 bottom
R2515  -  [VX_R0402_0OHM_SMALL]  166.93 65.93 90 top
R2516  -  [VX_R0402_SMALL]  158.42 54.62 270 top
R2517  -  [VX_R0402_0OHM_SMALL]  167.82 65.93 90 top
R2518  -  [VX_R0402_0OHM_SMALL]  165.66 68.21 90 bottom
R2519  -  [VX_R0402_0OHM_SMALL]  164.77 68.21 90 bottom
R2520  -  [VX_R0402_0OHM_SMALL]  166.8 70.37 90 bottom
R2521  -  [VX_R0402_0OHM_SMALL]  165.91 70.37 90 bottom
R2522  -  [VX_R0402_0OHM_SMALL]  153.59 61.94 180 bottom
R2523  -  [VX_R0402_SMALL]  185.09 62.83 270 bottom
R2524  -  [VX_R0402_SMALL]  153.59 62.83 180 bottom
R2525  -  [VX_R0402_0OHM_SMALL]  187 63.55 270 bottom
R2526  -  [VX_R0402_SMALL]  168.73 67.58 270 bottom
R2527  -  [VX_R0402_0OHM_SMALL]  165.23 65.9 90 top
R2528  -  [VX_R0402_0OHM_SMALL]  164.34 65.9 90 top
R2603  -  [VX_R0603_0OHM_H28_SMALL]  184.07 36.21 90 bottom
R2604  -  [VX_R0603_0OHM_H28_SMALL]  162.36 66.82 0 top
R2605  -  [VX_R0603_0OHM_H28_SMALL]  185.98 66.31 270 top
R2606  -  [VX_R0603_0OHM_H28_SMALL]  152.96 42.38 270 bottom
R2607  -  [VX_R0603_0OHM_H28_SMALL]  172.52 55.13 90 top
R2608  -  [VX_R0603_0OHM_H28_SMALL]  187.88 66.31 270 top
R2609  -  [VX_R0603_0OHM_H28_SMALL]  191.19 60.34 270 top
R2613  -  [VX_R1206_H31]  155.75 51.78 90 top
R2615  -  [VX_R0603_0OHM_H28_SMALL]  182.55 40.84 270 top
R2616  -  [VX_R0603_0OHM_H28_SMALL]  186.13 40.56 270 bottom
R2617  -  [VX_R0603_0OHM_H28_SMALL]  172.34 67.71 90 top
R2618  -  [VX_R0603_0OHM_H28_SMALL]  173.66 67.71 90 top
R2619  -  [VX_R0603_0OHM_H28_SMALL]  188.01 39.72 0 bottom
R2700  -  [VX_R0402_0OHM_SMALL]  171.25 67.58 90 top
R2701  -  [VX_R0402_0OHM_SMALL]  169.52 67.58 90 top
R2810  -  [VX_R0402_SMALL]  221.16 58.01 270 bottom
R2811  -  [VX_R0402_SMALL]  229.29 56.23 180 bottom
R2812  -  [VX_R0402_SMALL]  219.18 58.01 270 bottom
R3000  -  [VX_R0603_0OHM_H28_SMALL]  108.38 47.72 0 top
R3001  -  [VX_R0402_SMALL]  130.71 30.9 180 top
R3005  -  [VX_R0402_SMALL]  130.1 45.48 180 top
R3013  -  [VX_R0402_0OHM_SMALL]  125.27 48.27 270 top
R3014  -  [VX_R0402_0OHM_SMALL]  123.95 50.69 270 top
R3015  -  [VX_R0402_0OHM_SMALL]  123.06 50.69 270 top
R3016  -  [VX_R0402_0OHM_SMALL]  122.2 50.69 270 top
R3018  -  [VX_R0402_0OHM_SMALL]  125.64 50.69 270 top
R3020  -  [VX_R0402_0OHM_SMALL]  124.78 50.69 270 top
R3029  -  [VX_R0402_SMALL]  120.73 25.29 270 top
R3030  -  [VX_R0402_SMALL]  119.84 25.29 270 top
R3032  -  [VX_R0402_0OHM_SMALL]  130.1 35.55 0 top
R3033  -  [VX_R0402_0OHM_SMALL]  130.1 36.39 0 top
R3034  -  [VX_R0402_0OHM_SMALL]  130.1 39 180 top
R3035  -  [VX_R0402_0OHM_SMALL]  130.1 39.87 180 top
R3037  -  [VX_R0402_0OHM_SMALL]  118.42 50.77 90 top
R3041  -  [VX_R0402_SMALL]  130.2 31.79 180 top
R3043  -  [VX_R0402_SMALL]  130.2 33.49 180 top
R3044  -  [VX_R0402_SMALL]  130.2 32.63 180 top
R3047  -  [VX_R0603_0OHM_H28_SMALL]  113.72 25.75 90 top
R3048  -  [VX_R0603_0OHM_H28_SMALL]  116.08 25.52 90 top
R3053  -  [VX_R0402_SMALL]  130.1 42.71 180 top
R3061  -  [VX_R0402_SMALL]  117.4 50.77 270 top
R3062  -  [VX_R0402_SMALL]  118.42 48.02 270 top
R3063  -  [VX_R0402_SMALL]  116.68 48.15 270 top
R3064  -  [VX_R0402_SMALL]  117.53 48.02 270 top
R3065  -  [VX_R0402_SMALL]  130.1 41.9 180 top
R3066  -  [VX_R0402_SMALL]  130.1 37.23 180 top
R3069  -  [VX_R0402_0OHM_SMALL]  119.69 50.77 270 top
R3070  -  [VX_R0402_SMALL]  132.26 36.34 180 top
R3071  -  [VX_R0402_SMALL]  132.23 35.4 180 top
R3072  -  [VX_R0402_SMALL]  122.99 24.32 90 top
R3073  -  [VX_R0402_SMALL]  122.1 24.32 90 top
R3074  -  [VX_R0402_0OHM_SMALL]  112.83 22.95 0 top
R3075  -  [VX_R0402_0OHM_SMALL]  110.92 23.46 0 top
R3076  -  [VX_R0402_0OHM_SMALL]  109.02 43.53 0 top
R3077  -  [VX_R0402_0OHM_SMALL]  230.3 53.31 270 top
R3079  -  [VX_R0402_0OHM_SMALL]  121.11 26.94 270 top
R3080  -  [VX_R0402_0OHM_SMALL]  120.22 26.94 270 top
R3081  -  [VX_R0402_SMALL]  130.1 44.34 180 top
R3082  -  [VX_R0402_0OHM_SMALL]  115.57 48.15 270 top
R3084  -  [VX_R0402_0OHM_SMALL]  133.48 31.35 0 top
R3085  -  [VX_R0402_0OHM_SMALL]  105.72 23.59 180 top
R3086  -  [VX_R0402_0OHM_SMALL]  110.92 24.35 180 top
R3087  -  [VX_R0402_0OHM_SMALL]  99.11 24.3 180 top
R3088  -  [VX_R0402_0OHM_SMALL]  102.67 23.97 180 top
R3089  -  [VX_R0402_0OHM_SMALL]  117.15 25.29 270 top
R3090  -  [VX_R0402_0OHM_SMALL]  118.03 25.29 270 top
R3091  -  [VX_R0402_0OHM_SMALL]  117.27 22.46 180 top
R3092  -  [VX_R0402_0OHM_SMALL]  119.3 26.94 270 top
R3094  -  [VX_R0402_0OHM_SMALL]  128.65 28.85 0 top
R3095  -  [VX_R0402_0OHM_SMALL]  131.41 28.92 0 top
R3096  -  [VX_R0402_0OHM_SMALL]  132.72 27.96 270 top
R3097  -  [VX_R0402_0OHM_SMALL]  133.6 27.96 270 top
R3098  -  [VX_R0402_0OHM_SMALL]  132.89 40.35 0 top
R3104  -  [VX_R0402_SMALL]  151.44 33.37 180 top
R3105  -  [VX_R0402_SMALL]  154.31 32.89 180 top
R3108  -  [VX_R0402_0OHM_SMALL]  151.44 34.26 180 top
R3110  -  [VX_R0402_0OHM_SMALL]  154.31 32.07 180 top
R3112  -  [VX_R0402_SMALL]  157.71 30.32 0 top
R3114  -  [VX_R0402_SMALL]  157.71 29.43 0 top
R3116  -  [VX_R0402_SMALL]  196.65 43.19 270 top
R3124  -  [VX_R0402_SMALL]  196.14 26.89 90 top
R3137  -  [VX_R0402_0OHM_SMALL]  148.51 34.38 90 top
R3138  -  [VX_R0402_0OHM_SMALL]  146.1 25.75 0 top
R3139  -  [VX_R0402_0OHM_SMALL]  146.1 24.86 0 top
R3140  -  [VX_R0402_0OHM_SMALL]  146.1 30.45 180 top
R3141  -  [VX_R0402_SMALL]  143.69 30.83 270 top
R3142  -  [VX_R0402_SMALL]  146.1 31.34 0 top
R3143  -  [VX_R0402_SMALL]  142.8 30.83 270 top
R3144  -  [VX_R0402_SMALL]  146.1 29.56 0 top
R3145  -  [VX_R0402_SMALL]  141.91 30.83 270 top
R3146  -  [VX_R0402_SMALL]  146.1 28.67 0 top
R3147  -  [VX_R0402_SMALL]  141.02 31.51 270 top
R3148  -  [VX_R0402_SMALL]  146.1 27.78 0 top
R3149  -  [VX_R0402_0OHM_SMALL]  146.1 23.97 180 top
R3150  -  [VX_R0402_0OHM_SMALL]  176.73 31.64 90 bottom
R3151  -  [VX_R0402_0OHM_SMALL]  175.91 31.64 90 bottom
R3156  -  [VX_R0402_SMALL]  196.39 28.67 270 top
R3157  -  [VX_R0402_SMALL]  195.02 30.02 270 top
R3158  -  [VX_R0402_SMALL]  197.28 27.91 90 top
R3159  -  [VX_R0402_SMALL]  196.14 46.19 0 top
R3160  -  [VX_R0402_SMALL]  197.87 43.19 270 top
R3161  -  [VX_R0603_0OHM_H28_SMALL]  189.66 27.53 90 top
R3162  -  [VX_R0603_0OHM_H28_SMALL]  191.06 31.21 180 top
R3163  -  [VX_R0402_0OHM_SMALL]  170.05 29.7 0 bottom
R3164  -  [VX_R0402_0OHM_SMALL]  221.03 50.51 0 bottom
R3165  -  [VX_R0603_0OHM_H28_SMALL]  225.22 52.42 0 bottom
R3166  -  [VX_R0603_0OHM_H28_SMALL]  224.59 44.8 270 bottom
R3167  -  [VX_R0402_SMALL]  221.03 52.54 0 bottom
R3168  -  [VX_R0402_SMALL]  221.03 51.53 180 bottom
R3169  -  [VX_R0603_H28_SMALL]  226.11 47.46 270 bottom
R3170  -  [VX_R0603_0OHM_H28_SMALL]  223.83 43.78 0 top
R3301  -  [VX_R0402_SMALL]  238.05 89.3 270 top
R3303  -  [VX_R0402_0OHM_SMALL]  236.27 89.3 270 top
R3304  -  [VX_R0402_0OHM_SMALL]  237.16 89.3 270 top
R3305  -  [VX_R0402_0OHM_SMALL]  222.43 93.44 180 top
R3306  -  [VX_R0402_SMALL]  231.45 96.15 270 bottom
R3307  -  [VX_R0402_SMALL]  237.67 87.77 180 top
R3308  -  [VX_R0402_0OHM_SMALL]  235.38 86.76 270 top
R3309  -  [VX_R0603_0OHM_H28_SMALL]  223.32 92.34 0 bottom
R3400  -  [VX_R0402_SMALL]  254.69 146.95 0 top
R3401  -  [VX_R0402_SMALL]  254.69 144.54 0 top
R3402  -  [VX_R0402_SMALL]  254.69 141.49 0 top
R3403  -  [VX_R0402_SMALL]  254.69 138.44 0 top
R3404  -  [VX_R0603_0OHM_H28_SMALL]  247.07 142 0 bottom
R3600  -  [VX_R0402_SMALL]  14.78 72.28 90 top
R3603  -  [VX_R0402_SMALL]  22.02 74.44 90 top
R3604  -  [VX_R0402_SMALL]  10.26 65.67 180 top
R3605  -  [VX_R0603_0OHM_H28_SMALL]  25.59 60.09 90 top
R3606  -  [VX_R0402_SMALL]  20.37 79.47 180 top
R3607  -  [VX_R0402_SMALL]  21.34 80.83 90 top
R3608  -  [VX_R0402_SMALL]  10.26 66.56 180 top
R3609  -  [VX_R0603_0OHM_H28_SMALL]  24.4 76.86 270 top
R3610  -  [VX_R0402_0OHM_SMALL]  24.82 65.17 180 top
R3611  -  [VX_R0402_SMALL]  24.84 66.04 180 top
R3612  -  [VX_R0603_0OHM_H28_SMALL]  25.67 76.86 270 top
R3613  -  [VX_R0402_SMALL]  28.75 68.29 90 top
R3616  -  [VX_R0402_0OHM_SMALL]  27.86 68.29 270 top
R3620  -  [VX_R0402_0OHM_SMALL]  19.23 75.33 270 top
R3621  -  [VX_R0402_0OHM_SMALL]  14.66 76.98 0 bottom
R3622  -  [VX_R0402_0OHM_SMALL]  4.55 70.45 270 top
R3623  -  [VX_R0402_SMALL]  20.98 74.43 90 top
R3624  -  [VX_R0402_SMALL]  20.14 74.43 90 top
R3625  -  [VX_R0603_0OHM_H28_SMALL]  18.54 85.82 270 bottom
R3626  -  [VX_R0603_0OHM_H28_SMALL]  17.3 85.82 270 bottom
R3627  -  [VX_R0603_0OHM_H28_SMALL]  15.29 84.68 270 bottom
R3628  -  [VX_R0603_0OHM_H28_SMALL]  14.02 84.68 270 bottom
R3629  -  [VX_R0603_0OHM_H28_SMALL]  12.75 76.04 270 bottom
R3630  -  [VX_R0603_0OHM_H28_SMALL]  19.61 72.02 90 bottom
R3631  -  [VX_R0603_0OHM_H28_SMALL]  14.15 66.31 90 bottom
R3632  -  [VX_R0402_SMALL]  21.39 69.05 270 bottom
R3700  -  [VX_R0402_SMALL]  18.59 76.6 90 bottom
R3702  -  [VX_R0402_0OHM_SMALL]  200.58 35.91 270 bottom
R3704  -  [VX_R0402_SMALL]  17.58 76.6 90 bottom
R3707  -  [VX_R0402_0OHM_SMALL]  204.27 31.34 90 bottom
R3708  -  [VX_R0402_0OHM_SMALL]  203.38 31.34 90 bottom
R3709  -  [VX_R0402_0OHM_SMALL]  204.39 29.71 90 bottom
R3710  -  [VX_R0402_0OHM_SMALL]  200.28 29.23 180 bottom
R3711  -  [VX_R0402_SMALL]  19.48 76.6 270 bottom
R3712  -  [VX_R0402_SMALL]  16.36 76.91 180 bottom
R3713  -  [VX_R0603_0OHM_H28_SMALL]  199.31 30.65 0 top
R3714  -  [VX_R0603_0OHM_H28_SMALL]  198.81 27.91 270 top
R4301  -  [VX_R0402_0OHM_SMALL]  101.52 178.66 180 bottom
R4302  -  [VX_R0402_SMALL]  101.52 181.32 180 bottom
R4303  -  [VX_R0402_SMALL]  101.52 179.54 180 bottom
R4304  -  [VX_R0402_SMALL]  100.76 177.39 90 bottom
R4305  -  [VX_R0402_SMALL]  94.16 178.78 0 bottom
R4306  -  [VX_R0402_SMALL]  94.16 179.67 0 bottom
R4307  -  [VX_R0402_SMALL]  101.52 180.43 180 bottom
R4308  -  [VX_R0402_0OHM_SMALL]  101.52 182.21 180 bottom
R4309  -  [VX_R0402_SMALL]  94.16 181.45 0 bottom
R4310  -  [VX_R0402_SMALL]  94.41 182.59 0 bottom
R4311  -  [VX_R0402_SMALL]  94.16 180.56 0 bottom
R4312  -  [VX_R0402_SMALL]  100.25 175.86 0 bottom
R4313  -  [VX_R0603_0OHM_H28_SMALL]  95.05 179.16 90 top
R4314  -  [VX_R0603_0OHM_H28_SMALL]  100.76 179.8 180 top
R4400  -  [VX_R0603_0OHM_H28_SMALL]  8.18 129.81 90 top
R4401  -  [VX_R0603_0OHM_H28_SMALL]  3.48 129.68 90 top
R4402  -  [VX_R0402_0OHM_SMALL]  10.72 121.81 270 bottom
R4403  -  [VX_R0402_0OHM_SMALL]  12.65 143.65 90 bottom
R4404  -  [VX_R0402_SMALL]  6.91 121.81 90 bottom
R4405  -  [VX_R0402_SMALL]  6.91 120.11 270 bottom
R4406  -  [VX_R0402_SMALL]  7.95 118 270 bottom
R4407  -  [VX_R0402_0OHM_SMALL]  12.45 141.81 0 bottom
R4408  -  [VX_R0402_0OHM_SMALL]  11.61 139.84 90 bottom
R4409  -  [VX_R0402_SMALL]  8.94 121.81 270 bottom
R4410  -  [VX_R0402_SMALL]  7.06 118 90 bottom
R4411  -  [VX_R0402_SMALL]  9.83 118 90 bottom
R4412  -  [VX_R0402_SMALL]  8.97 118 90 bottom
R4413  -  [VX_R0402_0OHM_SMALL]  6.22 118 270 bottom
R4414  -  [VX_R0402_SMALL]  10.72 118 270 bottom
R4415  -  [VX_R0402_0OHM_SMALL]  8.03 120.11 270 bottom
R4416  -  [VX_R0402_SMALL]  8.94 120.11 270 bottom
R4417  -  [VX_R0402_0OHM_SMALL]  9.83 120.11 270 bottom
R4418  -  [VX_R0402_SMALL]  5.89 120.11 90 bottom
R4419  -  [VX_R0402_0OHM_SMALL]  4.12 119.14 270 bottom
R4420  -  [VX_R0402_0OHM_SMALL]  12.5 121.81 90 bottom
R4421  -  [VX_R0402_0OHM_SMALL]  11.61 121.81 90 bottom
R4422  -  [VX_R0402_SMALL]  10.95 143.65 90 bottom
R4423  -  [VX_R0402_0OHM_SMALL]  5.89 121.81 90 bottom
R4424  -  [VX_R0402_0OHM_SMALL]  11.81 143.65 270 bottom
R4425  -  [VX_R0402_SMALL]  3.23 119.14 270 bottom
R4426  -  [VX_R0402_0OHM_SMALL]  3.73 121.81 90 bottom
R4501  -  [VX_R0402_SMALL]  44.25 181.32 0 top
R4502  -  [VX_R0402_0OHM_SMALL]  57.84 183.99 180 bottom
R4503  -  [VX_R0603_0OHM_H28_SMALL]  50.71 174.8 90 bottom
R4504  -  [VX_R0402_0OHM_SMALL]  44.73 179.44 0 top
R4518  -  [VX_R0402_SMALL]  40.03 180.59 180 top
R4523  -  [VX_R0402_SMALL]  60.88 180.35 270 bottom
R4524  -  [VX_R0402_SMALL]  62.41 179.97 180 bottom
R4525  -  [VX_R0402_SMALL]  43.99 182.97 90 top
R4526  -  [VX_R0402_SMALL]  59.74 174.77 90 bottom
R4527  -  [VX_R0402_0OHM_SMALL]  42.72 184.12 0 top
R4586  -  [VX_R0402_SMALL]  62.28 184.67 270 bottom
R4587  -  [VX_R0402_SMALL]  44.25 180.43 180 top
R4588  -  [VX_R0402_SMALL]  59.74 176.37 90 bottom
R4590  -  [VX_R0402_0OHM_SMALL]  60.86 172.48 180 bottom
R4591  -  [VX_R0603_H28_SMALL]  55.42 179.29 90 bottom
R4592  -  [VX_R0402_SMALL]  41.58 178.66 0 top
R4593  -  [VX_R0402_SMALL]  38.41 183.99 180 top
R4594  -  [VX_R0603_0OHM_H28_SMALL]  34.82 183.13 0 top
R4601  -  [VX_R0402_SMALL]  238.05 110.46 270 top
R4602  -  [VX_R0402_SMALL]  237.16 110.46 90 top
R4603  -  [VX_R1206_H31]  236.27 113 0 top
R4604  -  [VX_R0402_SMALL]  246.3 100.42 270 top
R4607  -  [VX_R0402_SMALL]  250.62 112.69 180 top
R4608  -  [VX_R0402_SMALL]  250.62 113.93 180 top
R4609  -  [VX_R0402_SMALL]  248.34 100.3 90 top
R4610  -  [VX_R0402_SMALL]  251.71 115.13 0 top
R4621  -  [VX_R0402_SMALL]  240.08 111.6 90 top
R4623  -  [VX_R0402_SMALL]  244.53 100.42 90 top
R4624  -  [VX_R0402_SMALL]  245.42 100.42 270 top
R4625  -  [VX_R0402_SMALL]  243.64 100.3 90 top
R4626  -  [VX_R0402_SMALL]  242.75 100.3 270 top
R4627  -  [VX_R0402_SMALL]  250.62 111.85 180 top
R4628  -  [VX_R0402_0OHM_SMALL]  247.32 100.3 270 top
R4629  -  [VX_R0402_SMALL]  258.24 89.76 90 top
R4630  -  [VX_R0402_SMALL]  257.1 89.76 270 top
R4631  -  [VX_R0603_0OHM_H28_SMALL]  257.1 106.82 90 top
R4800  -  [VX_R0402_SMALL]  244.91 78.63 180 top
R4803  -  [VX_R0402_SMALL]  250.65 78.93 90 top
R4806  -  [VX_R0402_SMALL]  249.61 74.31 270 top
R4807  -  [VX_R0402_SMALL]  249.63 76.09 90 top
R4808  -  [VX_R0402_SMALL]  252.15 98.57 0 top
R4809  -  [VX_R0402_SMALL]  252.15 101.11 0 top
R4810  -  [VX_R0402_SMALL]  252.02 86.88 0 top
R4811  -  [VX_R0402_SMALL]  252.02 88.15 0 top
R4812  -  [VX_R0402_SMALL]  252.15 99.84 0 top
R4813  -  [VX_R0402_SMALL]  252.02 84.09 0 top
R4814  -  [VX_R0402_SMALL]  252.02 85.23 0 top
R4815  -  [VX_R0402_SMALL]  252.15 97.3 0 top
R4816  -  [VX_R0402_0OHM_SMALL]  244.91 77.61 0 top
R4817  -  [VX_R0402_SMALL]  250.67 76.16 90 top
R4818  -  [VX_R0402_SMALL]  250.67 74.47 270 top
R5000  -  [VX_R0402_SMALL]  41.71 111.27 90 bottom
R5001  -  [VX_R0402_SMALL]  178.36 75.96 180 top
R5002  -  [VX_R0402_SMALL]  178.36 74.7 180 top
R5003  -  [VX_R0402_SMALL]  39.55 110.89 180 bottom
R5004  -  [VX_R0402_SMALL]  123.09 54.02 180 top
R5005  -  [VX_R0402_SMALL]  37.9 110.89 180 bottom
R5006  -  [VX_R0402_SMALL]  41.71 112.92 90 bottom
R5007  -  [VX_R0402_SMALL]  191.39 83.63 90 bottom
R5008  -  [VX_R0402_SMALL]  190.53 83.68 90 bottom
R5009  -  [VX_R0402_SMALL]  190.53 85.28 90 bottom
R5010  -  [VX_R0402_SMALL]  191.39 85.28 90 bottom
R5011  -  [VX_R0402_SMALL]  173.15 73.12 180 top
R5012  -  [VX_R0402_SMALL]  24.94 119.85 270 top
R5013  -  [VX_R0402_SMALL]  186.61 81.04 180 top
R5014  -  [VX_R0402_SMALL]  118.23 53.78 90 top
R5015  -  [VX_R0402_SMALL]  29.26 111.77 180 top
R5016  -  [VX_R0402_SMALL]  183.69 75.33 90 top
R5017  -  [VX_R0402_SMALL]  231.19 98.9 180 bottom
R5018  -  [VX_R0402_SMALL]  227.89 100.68 270 bottom
R5104  -  [VX_R0402_0OHM_SMALL]  55.74 27.19 90 top
R5106  -  [VX_R0402_0OHM_SMALL]  56.62 27.19 90 top
R5108  -  [VX_R0402_0OHM_SMALL]  24.82 30.49 180 top
R5109  -  [VX_R0402_0OHM_SMALL]  25.07 28.41 90 top
R5115  -  [VX_R0402_SMALL]  54.68 27.22 270 top
R5122  -  [VX_R0402_0OHM_SMALL]  45.92 27.21 90 top
R5123  -  [VX_R0402_0OHM_SMALL]  44.37 27.73 0 top
R5124  -  [VX_R0402_0OHM_SMALL]  26.47 30.49 0 top
R5125  -  [VX_R0402_0OHM_SMALL]  28.17 27.74 0 top
R5126  -  [VX_R0402_0OHM_SMALL]  47.3 176.17 180 bottom
R5127  -  [VX_R0402_SMALL]  26.47 29.61 180 top
R5129  -  [VX_R0603_0OHM_H28_SMALL]  70.34 26.76 180 top
R5130  -  [VX_R0603_0OHM_H28_SMALL]  38.02 49.75 0 bottom
R5131  -  [VX_R0402_0OHM_SMALL]  39.29 46.83 180 bottom
R5132  -  [VX_R0402_SMALL]  24.82 29.61 180 top
R5134  -  [VX_R0402_SMALL]  160.96 29.94 270 top
R5136  -  [VX_R0402_SMALL]  155.27 27.16 270 top
R5137  -  [VX_R0402_SMALL]  26.85 43.4 270 top
R5139  -  [VX_R0402_SMALL]  159.31 30.32 0 top
R5200  -  [VX_R0402_SMALL]  257.1 58.77 0 top
R5201  -  [VX_R0402_SMALL]  257.1 59.66 0 top
R5202  -  [VX_R0402_0OHM_SMALL]  239.74 57.25 0 top
R5203  -  [VX_R0402_0OHM_SMALL]  237.03 56.74 0 top
R5204  -  [VX_R0402_0OHM_SMALL]  232.21 56.74 0 top
R5206  -  [VX_R0402_SMALL]  247.32 58.18 180 top
R5207  -  [VX_R0402_SMALL]  245.17 57.66 0 top
R5208  -  [VX_R0402_SMALL]  247.49 56.48 0 top
R5209  -  [VX_R0402_SMALL]  234.62 56.74 0 top
R5210  -  [VX_R0402_SMALL]  234.62 57.62 180 top
R5300  -  [VX_R0402_SMALL]  248.23 95.28 270 top
R5301  -  [VX_R0402_SMALL]  241.35 84.42 90 top
R5302  -  [VX_R0402_SMALL]  240.34 84.42 90 top
R5308  -  [VX_R0402_SMALL]  249.12 95.28 270 top
R5309  -  [VX_R0402_0OHM_SMALL]  249.99 95.26 90 top
R5310  -  [VX_R0402_0OHM_SMALL]  246.44 94.96 0 top
R5311  -  [VX_R0402_0OHM_SMALL]  246.44 94.12 180 top
R5312  -  [VX_R0402_0OHM_SMALL]  246.44 93.29 180 top
R5501  -  [VX_R0402_SMALL]  244.6 62.61 0 top
R5601  -  [VX_R0402_SMALL]  47.55 182.21 0 bottom
R5602  -  [VX_R0402_SMALL]  47.3 183.1 0 bottom
R5603  -  [VX_R0402_SMALL]  47.57 180.48 0 bottom
R5700  -  [VX_R0603_H28_SMALL]  152.32 130.32 0 bottom
R5701  -  [VX_R0603_H28_SMALL]  156.93 130.39 180 bottom
R5702  -  [VX_R0603_H28_SMALL]  147.12 133.62 90 bottom
R5703  -  [VX_R0603_H28_SMALL]  156.13 140.94 270 bottom
R5704  -  [VX_R0402_SMALL]  153.72 140.99 90 bottom
R5706  -  [VX_R0402_0OHM_SMALL]  152.45 140.98 270 bottom
R5707  -  [VX_R0603_H28_SMALL]  147.12 138.44 90 bottom
R5803  -  [VX_R0402_0OHM_SMALL]  246.3 126.63 0 top
R5804  -  [VX_R0402_0OHM_SMALL]  250.37 122.82 90 top
R5805  -  [VX_R0402_0OHM_SMALL]  254.56 126.63 180 top
R5806  -  [VX_R0402_SMALL]  246.3 127.52 180 top
R5807  -  [VX_R0402_0OHM_SMALL]  254.56 127.52 180 top
R5808  -  [VX_R0402_0OHM_SMALL]  251.26 122.82 90 top
R6001  -  [VX_R0402_SMALL]  229.54 21.05 0 bottom
R6003  -  [VX_R0603_0OHM_H28_SMALL]  237.21 25.99 180 bottom
R6004  -  [VX_R0603_0OHM_H28_SMALL]  237.21 27.26 180 bottom
R6005  -  [VX_R0603_0OHM_H28_SMALL]  255.19 67.96 0 bottom
R6006  -  [VX_R0402_SMALL]  251 65.63 90 bottom
R6101  -  [VX_R0402_SMALL]  162.1 33.29 90 bottom
R6102  -  [VX_R0402_SMALL]  162.23 36.34 270 bottom
R6103  -  [VX_R0402_SMALL]  160.71 33.29 90 bottom
R6104  -  [VX_R0402_SMALL]  161.34 36.34 270 bottom
R6113  -  [VX_R0402_SMALL]  161.34 33.67 90 top
R6114  -  [VX_R0402_SMALL]  161.34 36.34 270 top
R6115  -  [VX_R0402_SMALL]  154.23 33.67 90 bottom
R6116  -  [VX_R0402_SMALL]  154.36 36.34 270 bottom
R6117  -  [VX_R0402_SMALL]  162.23 33.67 90 top
R6118  -  [VX_R0402_SMALL]  163.12 33.67 270 top
R6119  -  [VX_R0402_SMALL]  157.79 33.42 90 bottom
R6120  -  [VX_R0402_SMALL]  157.79 36.34 270 bottom
R6121  -  [VX_R0402_SMALL]  159.56 33.29 90 bottom
R6122  -  [VX_R0402_SMALL]  159.56 36.34 270 bottom
R6123  -  [VX_R0402_SMALL]  158.67 33.42 90 bottom
R6124  -  [VX_R0402_SMALL]  158.67 36.34 270 bottom
R6201  -  [VX_R0603_0OHM_H28_SMALL]  184 30.6 270 top
R6202  -  [VX_R0603_0OHM_H28_SMALL]  177.88 30.38 0 top
R6737  -  [VX_R0402_SMALL]  14.02 69.99 90 bottom
R6738  -  [VX_R0402_SMALL]  14.91 69.99 90 bottom
R7000  -  [VX_R0402_SMALL]  96.19 120.03 0 top
R7001  -  [VX_R0402_SMALL]  86.03 129.55 180 bottom
R7002  -  [VX_R0402_0OHM_SMALL]  98.25 112.66 90 top
R7006  -  [VX_R0402_SMALL]  86.54 151.86 270 bottom
R7007  -  [VX_R0603_0OHM_H28_SMALL]  97.84 140.1 90 top
R7008  -  [VX_R0402_SMALL]  95.81 140.6 0 top
R7009  -  [VX_R0402_SMALL]  86.54 153.51 90 bottom
R7010  -  [VX_R0402_SMALL]  82.37 129.35 0 bottom
R7100  -  [VX_R0402_SMALL]  115.37 163.72 90 top
R7101  -  [VX_R0402_SMALL]  98.6 165.11 90 bottom
R7102  -  [VX_R0402_SMALL]  116.26 163.72 270 top
R7103  -  [VX_R0402_SMALL]  133.22 146.9 0 bottom
R7104  -  [VX_R0402_SMALL]  129.08 164.48 90 bottom
R7105  -  [VX_R0402_SMALL]  97.1 165.11 90 bottom
R7106  -  [VX_R0402_SMALL]  133.1 148.76 0 bottom
R7107  -  [VX_R0402_SMALL]  132.46 164.76 270 bottom
R7108  -  [VX_R0402_SMALL]  114.48 163.72 90 top
R7109  -  [VX_R0402_SMALL]  101.4 164.99 90 bottom
R7110  -  [VX_R0402_SMALL]  133.22 146.06 0 bottom
R7111  -  [VX_R0402_SMALL]  129.54 154.02 0 top
R7112  -  [VX_R0402_SMALL]  132.87 122.57 0 top
R7113  -  [VX_R0402_SMALL]  133.2 143.25 0 bottom
R7114  -  [VX_R0402_SMALL]  133.25 144.77 180 bottom
R7115  -  [VX_R0402_SMALL]  108 117.74 90 bottom
R7116  -  [VX_R0402_SMALL]  128.05 119.43 270 top
R7117  -  [VX_R0402_SMALL]  132.71 124.08 180 top
R7118  -  [VX_R0402_SMALL]  109.14 117.74 270 bottom
R7119  -  [VX_R0402_SMALL]  127.16 119.43 90 top
R7120  -  [VX_R0402_SMALL]  132.71 124.91 0 top
R7121  -  [VX_R0402_SMALL]  133.2 142.38 0 bottom
R7122  -  [VX_R0402_SMALL]  111.05 117.74 270 bottom
R7123  -  [VX_R0402_SMALL]  124 119.39 270 top
R7206  -  [VX_R0402_0OHM_SMALL]  79.68 151.53 90 top
R7208  -  [VX_R0402_SMALL]  92.89 114.77 90 bottom
R7210  -  [VX_R0402_SMALL]  93.66 117.44 90 bottom
R7211  -  [VX_R0402_SMALL]  93.75 114.77 270 bottom
R7212  -  [VX_R0402_SMALL]  94.54 133.11 0 top
R7213  -  [VX_R0402_SMALL]  92.63 122.44 0 top
R7214  -  [VX_R0402_SMALL]  91.11 122.44 180 top
R7215  -  [VX_R0603_0OHM_H28_SMALL]  98.48 135.22 90 top
R7216  -  [VX_R0402_SMALL]  234.75 119.47 0 top
R7217  -  [VX_R0402_SMALL]  234.75 115.79 0 top
R7218  -  [VX_R0402_SMALL]  234.75 121.38 0 top
R7219  -  [VX_R0402_0OHM_SMALL]  243.38 112.87 270 top
R7220  -  [VX_R0402_0OHM_SMALL]  242.49 112.87 270 top
R7304  -  [VX_R0402_SMALL]  86.54 127.78 180 top
R7305  -  [VX_R0402_SMALL]  86.54 126 180 top
R7306  -  [VX_R0402_SMALL]  82.22 120.66 270 top
R7307  -  [VX_R0402_SMALL]  84.37 126.06 0 bottom
R7308  -  [VX_R0402_SMALL]  84.2 129.35 0 bottom
R7309  -  [VX_R0402_SMALL]  84.42 127.17 0 bottom
R7310  -  [VX_R0402_SMALL]  83.26 128.01 0 bottom
R7311  -  [VX_R0402_SMALL]  84.38 124.09 0 bottom
R7312  -  [VX_R0402_SMALL]  86.54 128.67 180 top
R7313  -  [VX_R0402_SMALL]  86.54 125.11 0 top
R7314  -  [VX_R0402_SMALL]  81.33 120.66 270 top
R7315  -  [VX_R0402_SMALL]  86.03 125.11 0 bottom
R7316  -  [VX_R0402_SMALL]  86.03 128.67 0 bottom
R7317  -  [VX_R0402_SMALL]  86.03 126.89 0 bottom
R7318  -  [VX_R0402_SMALL]  86.03 127.78 0 bottom
R7319  -  [VX_R0402_SMALL]  86.03 124.22 0 bottom
R7400  -  [VX_R0402_SMALL]  86.54 123.33 0 top
R7401  -  [VX_R0402_SMALL]  86.54 124.22 180 top
R7402  -  [VX_R0402_SMALL]  76.63 126.38 0 top
R7403  -  [VX_R0402_SMALL]  76.63 125.11 0 top
R7404  -  [VX_R0201_H10]  86.03 126 180 bottom
R7405  -  [VX_R0402_SMALL]  86.03 122.06 180 bottom
R7406  -  [VX_R0402_SMALL]  86.03 120.92 180 bottom
R7407  -  [VX_R0402_SMALL]  86.03 123.33 180 bottom
R7408  -  [VX_R0402_SMALL]  92.84 117.44 90 bottom
R7409  -  [VX_R0402_SMALL]  83.67 120.06 90 bottom
R7410  -  [VX_R0402_SMALL]  83.67 118.4 270 bottom
R7411  -  [VX_R0402_SMALL]  86.54 129.63 180 top
R7414  -  [VX_R0402_SMALL]  98.48 119.98 270 top
R7419  -  [VX_R0402_SMALL]  99.62 117.62 90 bottom
R7423  -  [VX_R0402_SMALL]  101.4 114.95 270 bottom
R7425  -  [VX_R0402_SMALL]  86.41 134.13 90 bottom
R7429  -  [VX_R0402_SMALL]  103.18 117.62 90 bottom
R7435  -  [VX_R0402_SMALL]  102.54 115.33 90 bottom
R7436  -  [VX_R0402_SMALL]  104.17 117.62 270 bottom
R7437  -  [VX_R0402_SMALL]  100.51 114.95 270 bottom
R7438  -  [VX_R0402_SMALL]  99.64 114.94 90 bottom
